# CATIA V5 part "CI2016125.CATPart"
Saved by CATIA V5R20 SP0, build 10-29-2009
Part number: CI2016125
Bounding box of the stored display mesh (mm): x -15 to 15, y -11.069 to 149, z -20.511 to 16.572
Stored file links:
  C:\Users\Raffaele\Desktop\3D X SITO CF\BOLEX\19-INCLINED ASSEMBLY REF_CI\CI2016125.CATPart

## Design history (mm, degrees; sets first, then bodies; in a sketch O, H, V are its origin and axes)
Set1
  DatumSurface1 to DatumSurface16 "MANIFOLD_SOLID_BREP #385"
  DatumSurface17 to DatumSurface39 "MANIFOLD_SOLID_BREP #1110"
Body1 (main body)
